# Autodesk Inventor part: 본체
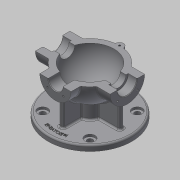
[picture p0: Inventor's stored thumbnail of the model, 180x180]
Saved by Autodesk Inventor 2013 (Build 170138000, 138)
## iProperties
Created: 2015-12
Part Number: 본체
Material: 알루미늄 6061
Document SubType Name: Modeling
Designer: mduedu
Density: 2.71 g/cm^3
Mass: 1103.17 g
Surface Area: 905.391 cm^2
Volume: 407.074 cm^3
Author: mduedu
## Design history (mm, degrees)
sketch "스케치1"
  geometry: L1 (-53, 0)-(53, 0); A1 r 53 centre (0, 0) between (53, 0) and (-53, 0); 2 further points
  constraints: 2 coincident, 2 end point, 2 point on circle, 1 centre point, 1 horizontal, 1 midpoint
  dimensions: "d0" = 53 radius of A1
revolve "회전1" sketch "스케치1" stored, may be unused: angle "d2" = 90 deg
feature "쉘1" dims "d11" = 10
node "작업 평면1"
sketch "스케치2"
  geometry: C1 r 31 at (0, 0); 1 further point
  constraints: 1 centre point, 1 coincident
  dimensions: "d4" = 62 diameter of C1
extrude "돌출1" join sketch "스케치2" stored distance "d5" = 10; taper "d6" = 0 deg
node "작업 평면2"
sketch "스케치3"
  geometry: C1 r 28 at (0, 0); 1 further point
  constraints: 1 centre point, 1 coincident
  dimensions: "d8" = 56 diameter of C1
extrude "돌출2" join sketch "스케치3" stored distance "d9" = 10; taper "d10" = 0 deg
hole "구멍1" diameter "d14" = 35; stored, may be unused: countersink angle "d18" = 90 deg, drill point angle "d20" = 0 deg; dims "d12" = 10, "d13" = 10, "d15" = 6, "d16" = 4, "d17" = 2, "d19" = 16
hole "구멍2" diameter "d23" = 27; stored, may be unused: countersink angle "d27" = 90 deg, drill point angle "d29" = 0 deg; dims "d21" = 10, "d22" = 10, "d24" = 6, "d25" = 4, "d26" = 2, "d28" = 16
fillet "모깎기1" dims "d30" = 0.3
hole "구멍3" diameter "d33" = 26; stored, may be unused: countersink angle "d37" = 90 deg, drill point angle "d39" = 0 deg; dims "d31" = 10, "d32" = 10, "d34" = 6, "d35" = 4, "d36" = 2, "d38" = 16
chamfer "모따기1" distance "d40" = 1; stored, may be unused: second distance "d41" = 2, angle "d42" = 45 deg
sketch "스케치4"
  geometry: L1 (0, 0)-(0, -25); L2 (0, 0)-(-17.678, -17.678); A1 r 25 centre (0, 0) between (-17.678, -17.678) and (0, -25); 1 further point
  constraints: 4 end point, 2 point on circle, 1 centre point, 1 coincident, 1 vertical
  dimensions: "d43" = 50 diameter of A1; "d47" = 45 deg angle of L1 L2
hole "구멍4" sketch "스케치4" at (-17.678, -17.678) diameter "d49" = 3.242; stored, may be unused: countersink angle "d53" = 90 deg, drill point angle "d55" = 118 deg; dims "d50" = 11, "d51" = 4, "d52" = 2, "d54" = 13
sketch "스케치5"
  geometry: L1 (0, 0)-(0, -20); L2 (0, 0)-(-14.142, -14.142); A1 r 20 centre (0, 0) between (0, -20) and (-14.142, -14.142); 2 further points
  constraints: 4 end point, 2 coincident, 2 point on circle, 1 centre point, 1 vertical
  dimensions: "d59" = 40 diameter of A1; "d65" = 45 deg angle of L1 L2
hole "구멍5" sketch "스케치5" at (-14.142, -14.142) diameter "d67" = 3.242; stored, may be unused: countersink angle "d71" = 90 deg, drill point angle "d73" = 118 deg; dims "d68" = 8, "d69" = 4, "d70" = 2, "d72" = 10
node "작업 평면3"
sketch "스케치6"
  geometry: C1 r 75 at (0, 0); 1 further point
  constraints: 1 centre point, 1 coincident
  dimensions: "d78" = 150 diameter of C1
extrude "돌출3" join sketch "스케치6" distance "d80" = 10; taper "d81" = 0 deg
sketch "스케치7"
  geometry: C1 r 20 at (0, 0); 1 further point
  constraints: 1 centre point, 1 coincident
  dimensions: "d82" = 40 diameter of C1
extrude "돌출4" join sketch "스케치7" stored distance "d84" = 10; taper "d85" = 0 deg
sketch "스케치8"
  geometry: 2 further points
  constraints: 1 coincident
hole "구멍6" sketch "스케치8" at (0, 0) diameter "d86" = 20; stored, may be unused: countersink angle "d90" = 90 deg, drill point angle "d92" = 118 deg; dims "d87" = 7, "d88" = 40, "d89" = 5, "d91" = 10
fillet "모깎기2" dims "d93" = 0.3
sketch "스케치9"
  geometry: L1 (-67, -18.5)-(-66, -17.5) reference; L2 (-66, -17.5)-(-51.3, -17.5) reference; L3 (-51, -17.2)-(-51, -13.5) reference; L4 (-51, -13.5)-(-40.826, -13.5) reference; L5 (-10, -41.821)-(-10, -80) reference; L6 (-10, -80)-(-19.7, -80) reference; L7 (-20, -80.3)-(-20, -85) reference; L8 (-20, -85)-(-75, -85) reference; L9 (-75, -85)-(-75, -75) reference; L10 (-75, -75)-(-20, -75) reference; L11 (-20, -75)-(-20, -49.082) reference; L12 (-42.988, -31)-(-67, -31) reference; L13 (-67, -31)-(-67, -18.5) reference; L14 (66, -17.5)-(67, -18.5) reference; L15 (67, -18.5)-(67, -31) reference; L16 (67, -31)-(42.988, -31) reference; L17 (20, -49.082)-(20, -75) reference; L18 (20, -75)-(75, -75) reference; L19 (75, -75)-(75, -85) reference; L20 (75, -85)-(20, -85) reference; L21 (20, -85)-(20, -80.3) reference; L22 (19.7, -80)-(10, -80) reference; L23 (10, -80)-(10, -41.821) reference; L24 (40.826, -13.5)-(51, -13.5) reference; L25 (51, -13.5)-(51, -17.2) reference; L26 (51.3, -17.5)-(66, -17.5) reference; L27 (67, 18.5)-(66, 17.5) reference; L28 (66, 17.5)-(51.3, 17.5) reference; L29 (51, 17.2)-(51, 13.5) reference; L30 (51, 13.5)-(40.826, 13.5) reference; L31 (-40.826, 13.5)-(-51, 13.5) reference; L32 (-51, 13.5)-(-51, 17.2) reference; L33 (-51.3, 17.5)-(-66, 17.5) reference; L34 (-66, 17.5)-(-67, 18.5) reference; L35 (-67, 18.5)-(-67, 31) reference; L36 (-67, 31)-(-42.988, 31) reference; L37 (42.988, 31)-(67, 31) reference; L38 (67, 31)-(67, 18.5) reference; L39 (-57, -31)-(-57, -75); A1 r 0.3 centre (-51.3, -17.2) between (-51.3, -17.5) and (-51, -17.2) reference; A2 r 43 centre (0, 0) between (-40.826, -13.5) and (-10, -41.821) reference; A3 r 0.3 centre (-19.7, -80.3) between (-19.7, -80) and (-20, -80.3) reference; A4 r 53 centre (0, 0) between (-42.988, -31) and (-20, -49.082) reference; A5 r 53 centre (0, 0) between (20, -49.082) and (42.988, -31) reference; A6 r 0.3 centre (19.7, -80.3) between (20, -80.3) and (19.7, -80) reference; A7 r 43 centre (0, 0) between (10, -41.821) and (40.826, -13.5) reference; A8 r 0.3 centre (51.3, -17.2) between (51, -17.2) and (51.3, -17.5) reference; A9 r 0.3 centre (51.3, 17.2) between (51.3, 17.5) and (51, 17.2) reference; A10 r 43 centre (0, 0) between (40.826, 13.5) and (-40.826, 13.5) reference; A11 r 0.3 centre (-51.3, 17.2) between (-51, 17.2) and (-51.3, 17.5) reference; A12 r 53 centre (0, 0) between (42.988, 31) and (-42.988, 31) reference; 1 further point
  constraints: 2 end point, 2 point on line, 1 perpendicular
  dimensions: "d151" = 10 distance between parallel lines of L39 L13
feature "리브1" sketch "스케치9" dims "d96" = 1, "d97" = 8, "d98" = 0, "d99" = 0, "d100" = 1, "d101" = 1
sketch "스케치14"
  geometry: L1 (-14, 62)-(-13, 61) reference; L2 (-13, 61)-(-13, 40.988) reference; L3 (-41.821, 10)-(-80, 10) reference; L4 (-80, 10)-(-80, 19.7) reference; L5 (-80.3, 20)-(-85, 20) reference; L6 (-85, 20)-(-85, 75) reference; L7 (-85, 75)-(-75, 75) reference; L8 (-75, 75)-(-75, 20) reference; L9 (-75, 20)-(-49.082, 20) reference; L10 (-28, 45)-(-28, 62) reference; L11 (-28, 62)-(-14, 62) reference; L12 (13, 61)-(14, 62) reference; L13 (14, 62)-(28, 62) reference; L14 (28, 62)-(28, 45) reference; L15 (-49.082, -20)-(-75, -20) reference; L16 (-75, -20)-(-75, -75) reference; L17 (-75, -75)-(-85, -75) reference; L18 (-85, -75)-(-85, -20) reference; L19 (-85, -20)-(-80.3, -20) reference; L20 (-80, -19.7)-(-80, -10) reference; L21 (-80, -10)-(-41.821, -10) reference; L22 (13, 40.988)-(13, 61) reference; L23 (-28, 52)-(-75, 52); A1 r 43 centre (0, 0) between (-13, 40.988) and (-41.821, 10) reference; A2 r 0.3 centre (-80.3, 19.7) between (-80, 19.7) and (-80.3, 20) reference; A3 r 53 centre (0, 0) between (-28, 45) and (-49.082, 20) reference; A4 r 53 centre (0, 0) between (0, -53) and (28, 45) reference; A5 r 53 centre (0, 0) between (-49.082, -20) and (0, -53) reference; A6 r 0.3 centre (-80.3, -19.7) between (-80.3, -20) and (-80, -19.7) reference; A7 r 43 centre (0, 0) between (-41.821, -10) and (0, -43) reference; A8 r 43 centre (0, 0) between (0, -43) and (13, 40.988) reference; 1 further point
  constraints: 2 end point, 2 point on line, 1 perpendicular
  dimensions: "d152" = 10 distance between parallel lines of L23 L11
feature "리브2" sketch "스케치14" dims "d153" = 1, "d154" = 8, "d155" = 0, "d156" = 0, "d157" = 1, "d158" = 1
sketch "스케치10"
  geometry: L1 (0, 0)-(0, -60); L2 (0, 0)-(-42.426, -42.426); A1 r 60 centre (0, 0) between (0, -60) and (-42.426, -42.426); 2 further points
  constraints: 4 end point, 2 coincident, 2 point on circle, 1 centre point, 1 vertical
  dimensions: "d105" = 120 diameter of A1; "d107" = 45 deg angle of L1 L2
hole "구멍7" sketch "스케치10" at (-42.426, -42.426) diameter "d109" = 10; stored, may be unused: countersink angle "d113" = 90 deg, drill point angle "d115" = 118 deg; dims "d110" = 7, "d111" = 18, "d112" = 4, "d114" = 10
fillet "모깎기3" dims "d120" = 3
fillet "모깎기4" dims "d121" = 3, "d122" = 3
fillet "모깎기5" dims "d123" = 3
fillet "모깎기6" dims "d124" = 3
sketch "스케치11"
  geometry: C1 r 75 at (0, 0) reference; C2 r 65 at (0, 0)
  constraints: 1 centre point, 1 coincident, 1 other
  dimensions: "d161" = 130 diameter of C2
feature "엠보싱1" sketch "스케치11" dims "d11" = 10, "d125" = 0.5, "d126" = 0
sketch "스케치12"
  geometry: L1 (0, 100)-(0, -100); L2 (0, 100)-(100, 100); L3 (100, 100)-(100, -100); L4 (100, -100)-(0, -100); 2 further points
  constraints: 8 end point, 3 perpendicular, 1 coincident, 1 midpoint, 1 vertical
  dimensions: "d127" = 200 distance of L2.end L3.end; "d129" = 100 distance between parallel lines of L1 L3
extrude "돌출5" cut sketch "스케치12" stored distance "d130" = 10; taper "d131" = 0 deg
sketch "스케치13"
  geometry: C1 r 7 at (0, 53); A1 r 53 centre (0, 0) between (42.113, 32.179) and (-42.113, 32.179) reference; 1 further point
  constraints: 1 centre point, 1 point on circle
  dimensions: "d132" = 14 diameter of C1
extrude "돌출6" join sketch "스케치13" distance "d134" = 15; taper "d135" = 0 deg
hole "구멍8" diameter "d139" = 3.242; stored, may be unused: countersink angle "d143" = 90 deg, drill point angle "d145" = 118 deg; dims "d140" = 8, "d141" = 4, "d142" = 2, "d144" = 10, "d148" = 10, "d149" = 10
fillet "모깎기7" dims "d146" = 3
fillet "모깎기8" dims "d147" = 3
node "솔리드1"
mirror "대칭1"
mirror "대칭2"
pattern_circular "원형 패턴1" dims angle "d57" = 360 deg
mirror "대칭3"
pattern_circular "원형 패턴2" dims angle "d75" = 360 deg
mirror "대칭4"
pattern_circular "원형 패턴4" dims angle "d118" = 360 deg
node "절단 모서리 투영1"
node "절단 모서리 투영2"
other parameters: "d3" = 67, "d7" = 62, "d77" = -85
